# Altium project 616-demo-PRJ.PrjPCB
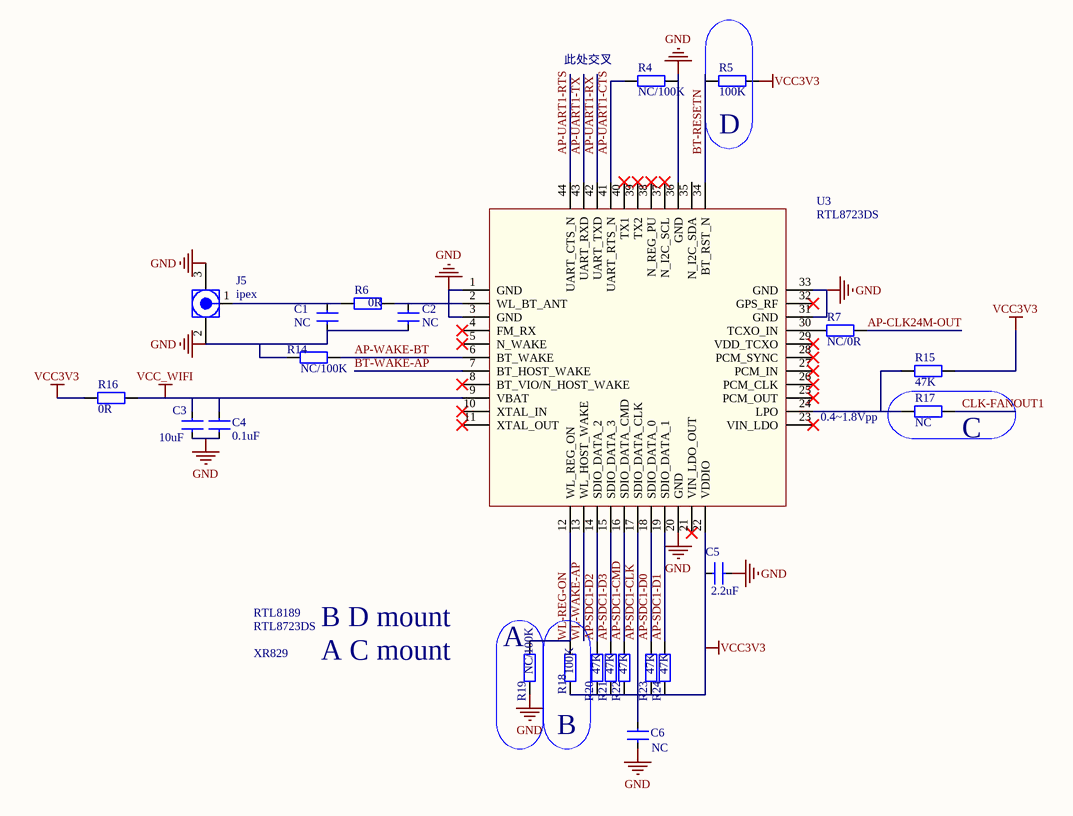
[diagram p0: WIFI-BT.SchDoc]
2 sheets, 70 parts. Net scope: global (net labels, ports and power ports of the same name join across sheets).
Board file: 616DEMO.PcbDoc
Sheets:
  WIFI-BT.SchDoc
  D1-Periph.SchDoc

## Sheet WIFI-BT.SchDoc
size A3

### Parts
C1  NC  [C0402]
C2  NC  [C0402]
C3  10uF  [C0402]
C4  0.1uF  [C0402]
C5  2.2uF  [C0402]
C6  NC  [C0402]
J5  ipex  [I-PEX SOCKET]
R4  NC/100K  [R0402]
R5  100K  [R0402]
R6  0R  [R0402]
R7  NC/0R  [R0402]
R14  NC/100K  [R0402]
R15  47K  [R0402]
R16  0R  [R0402]
R17  NC  [R0402]
R18  100K  [R0402]
R19  NC/100K  [R0402]
R20  47K  [R0402]
R21  47K  [R0402]
R22  47K  [R0402]
R23  47K  [R0402]
R24  47K  [R0402]
U3  RTL8723DS  [RTL8723DS]

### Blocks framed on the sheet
D: R5
A: R19
B: R18

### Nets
GND: C1.1 C2.1 C3.1 C4.1 C5.1 C6.1 J5.2(GND) J5.3(GND) R4.1 R14.2 R19.1 U3.1(GND) U3.3(GND) U3.20(GND) U3.31(GND) U3.33(GND) U3.36(GND)
VCC3V3: C5.2 R5.1 R15.2 R16.2 R18.1 R20.1 R21.1 R22.1 R23.1 R24.1 U3.22(VDDIO)
VCC_WIFI: C3.2 C4.2 R16.1 U3.9(VBAT)
AP-CLK24M-OUT: R7.1
AP-SDC1-CLK: C6.2 U3.17(SDIO_DATA_CLK)
AP-SDC1-CMD: R22.2 U3.16(SDIO_DATA_CMD)
AP-SDC1-D0: R23.2 U3.18(SDIO_DATA_0)
AP-SDC1-D1: R24.2 U3.19(SDIO_DATA_1)
AP-SDC1-D2: R20.2 U3.14(SDIO_DATA_2)
AP-SDC1-D3: R21.2 U3.15(SDIO_DATA_3)
AP-UART1-CTS: R4.2 U3.41(UART_RTS_N)
AP-UART1-RTS: U3.44(UART_CTS_N)
AP-UART1-RX: U3.42(UART_TXD)
AP-UART1-TX: U3.43(UART_RXD)
AP-WAKE-BT: R14.1 U3.6(BT_WAKE)
BT-RESETN: R5.2 U3.34(BT_RST_N)
BT-WAKE-AP: U3.7(BT_HOST_WAKE)
CLK-FANOUT1: R17.1
WL-REG-ON: R18.2 R19.2 U3.12(WL_REG_ON)
WL-WAKE-AP: U3.13(WL_HOST_WAKE)
NetC1_2: C1.2 J5.1(Signal) R6.2
NetC2_2: C2.2 R6.1 U3.2(WL_BT_ANT)
NetR7_2: R7.2 U3.30(TCXO_IN)
NetR15_1: R15.1 R17.2 U3.24(LPO)

Not connected (* = marked no-connect by the designer): U3 4(FM_RX)* 5(N_WAKE)* 8(BT_VIO/N_HOST_WAKE)* 10(XTAL_IN)* 11(XTAL_OUT)* 21(VIN_LDO_OUT)* 23(VIN_LDO)* 25(PCM_OUT)* 26(PCM_CLK)* 27(PCM_IN)* 28(PCM_SYNC)* 29(VDD_TCXO)* 32(GPS_RF)* 35(N_I2C_SDA) 37(N_I2C_SCL)* 38(N_REG_PU)* 39(TX2)* 40(TX1)*

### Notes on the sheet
- (near R4) 此处交叉
- 0.4
  .8Vpp
- (near R17) C
- RTL8723DS
- XR829
- RTL8189
- B D mount
- A C mount

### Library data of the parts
C1-C6 = CAP: 普通小电容
J5 = MCX_IPEX
R4-R7 R14-R24 = RES: 普通电阻
U3 = AP6212

## Sheet D1-Periph.SchDoc
size A3; DocumentNumber: 3; SheetNumber: 3; SheetTotal: 7
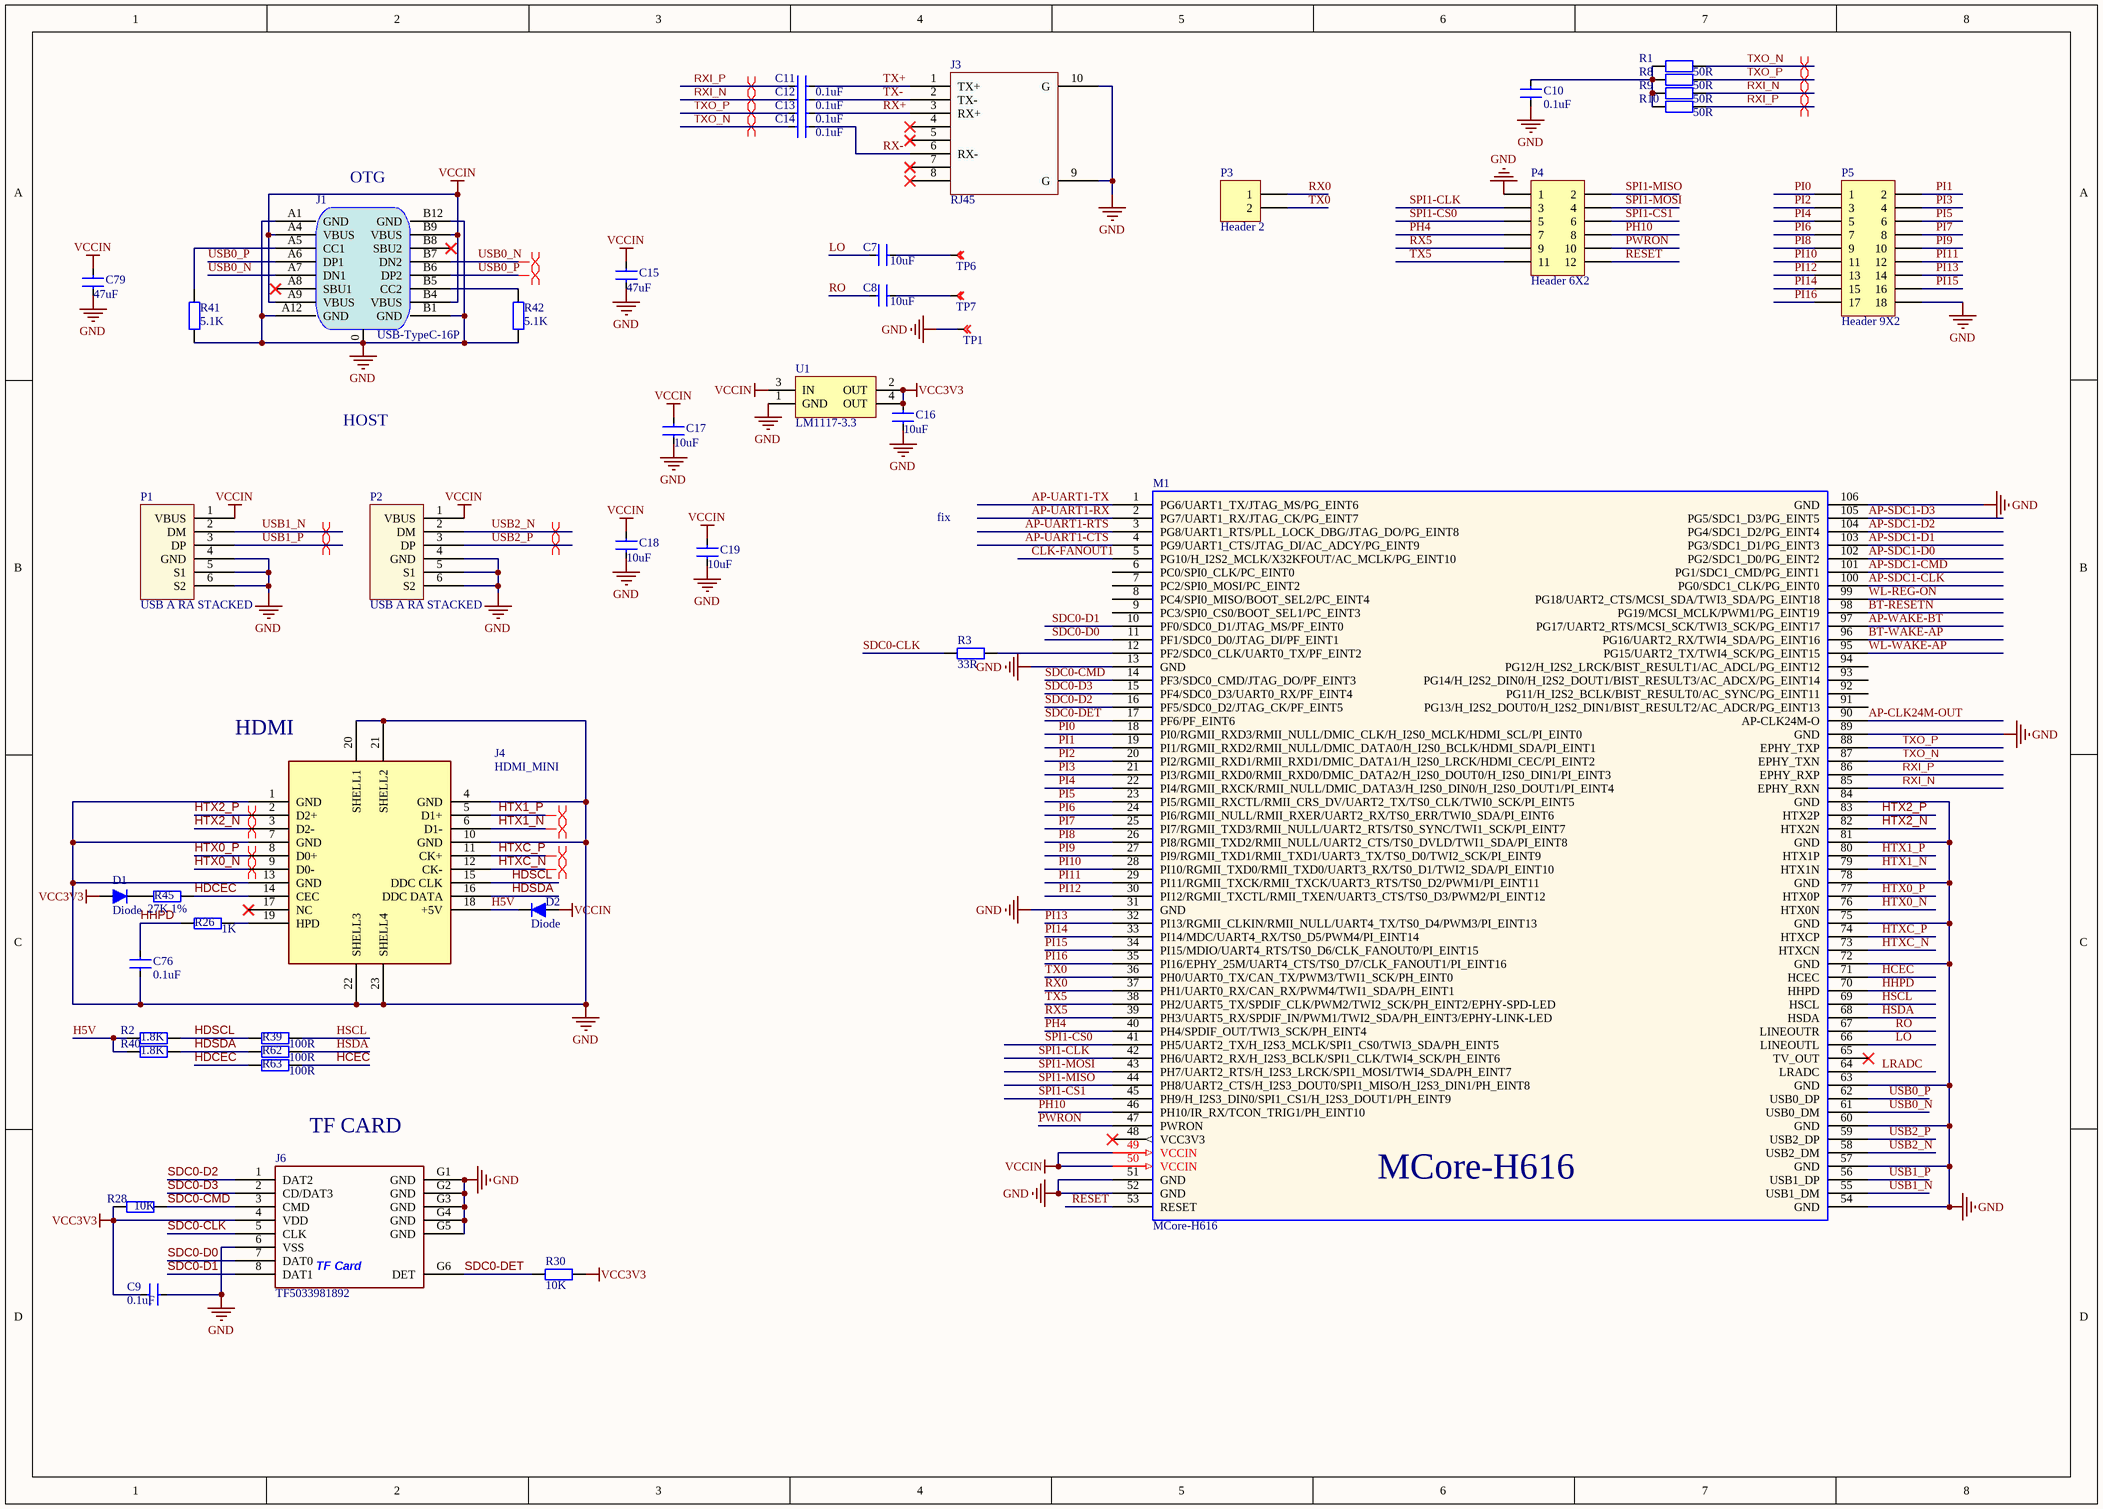
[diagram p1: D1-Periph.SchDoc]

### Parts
C7  10uF  [C0402]
C8  10uF  [C0402]
C9  0.1uF  [C0402]
C10  0.1uF  [C0402]
C11  0.1uF  [C0402]
C12  0.1uF  [C0402]
C13  0.1uF  [C0402]
C14  0.1uF  [C0402]
C15  47uF  [C0603]
C16  10uF  [C0402]
C17  10uF  [C0402]
C18  10uF  [C0402]
C19  10uF  [C0402]
C76  0.1uF  [C0402]
C79  47uF  [C0603]
D1  Diode  [SOD523]
D2  Diode  [SOD523]
J1  USB-TypeC-16P  [usb-typec-16p]
J3  RJ45  [RJ45]
J4  HDMI_MINI  [HDMI_T _mini]
J6  TF5033981892  [TFCARD-1040310811]
M1  MCore-H616  [MCore-H616]
P1  USB A RA STACKED  [USB-A STAND]
P2  USB A RA STACKED  [USB-A STAND]
P3  Header 2  [HDR1X2]
P4  Header 6X2  [HDR2X6]
P5  Header 9X2  [HDR2X9]
R1  50R  [R0402]
R2  1.8K  [R0402]
R3  33R  [R0402]
R8  50R  [R0402]
R9  50R  [R0402]
R10  50R  [R0402]
R26  1K  [R0402]
R28  10K  [R0402]
R30  10K  [R0402]
R39  100R  [R0402]
R40  1.8K  [R0402]
R41  5.1K  [R0402]
R42  5.1K  [R0402]
R45  27K 1%  [R0402]
R62  100R  [R0402]
R63  100R  [R0402]
TP1  TEST POINT  [TEST-POINT1.5]  (value not drawn)
TP6  TEST POINT  [TEST-POINT1.5]  (value not drawn)
TP7  TEST POINT  [TEST-POINT1.5]  (value not drawn)
U1  LM1117-3.3  [SOT223-4N]

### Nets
GND: C9.2 C10.1 C15.2 C16.2 C17.2 C18.2 C19.2 C76.1 C79.2 J1.0 J1.A1(GND) J1.A12(GND) J1.B1(GND) J1.B12(GND) J3.9(G) J3.10(G) J4.1(GND) J4.4(GND) J4.7(GND) J4.10(GND) J4.13(GND) J4.20(SHELL1) J4.21(SHELL2) J4.22(SHELL3) J4.23(SHELL4) J6.6(VSS) J6.G1(GND) J6.G2(GND) J6.G3(GND) J6.G4(GND) J6.G5(GND) M1.13(GND) M1.31(GND) M1.51(GND) M1.52(GND) M1.54(GND) M1.57(GND) M1.60(GND) M1.63(GND) M1.72(GND) M1.75(GND) M1.78(GND) M1.81(GND) M1.84(GND) M1.89(GND) M1.106(GND) P1.4(GND) P1.5(S1) P1.6(S2) P2.4(GND) P2.5(S1) P2.6(S2) P4.1 P5.18 R41.1 R42.1 TP1.1 U1.1(GND)
VCC3V3: C9.1 C16.1 D1.A J6.4(VDD) R28.1 R30.1 U1.2(OUT) U1.4(OUT)
VCCIN: C15.1 C17.1 C18.1 C19.1 C79.1 D2.A J1.A4(VBUS) J1.A9(VBUS) J1.B4(VBUS) J1.B9(VBUS) M1.49(VCCIN) M1.50(VCCIN) P1.1(VBUS) P2.1(VBUS) U1.3(IN)
AP-CLK24M-OUT: M1.90(AP-CLK24M-O)
AP-SDC1-CLK: M1.100(PG0/SDC1_CLK/PG_EINT0)
AP-SDC1-CMD: M1.101(PG1/SDC1_CMD/PG_EINT1)
AP-SDC1-D0: M1.102(PG2/SDC1_D0/PG_EINT2)
AP-SDC1-D1: M1.103(PG3/SDC1_D1/PG_EINT3)
AP-SDC1-D2: M1.104(PG4/SDC1_D2/PG_EINT4)
AP-SDC1-D3: M1.105(PG5/SDC1_D3/PG_EINT5)
AP-UART1-CTS: M1.4(PG9/UART1_CTS/JTAG_DI/AC_ADCY/PG_EINT9)
AP-UART1-RTS: M1.3(PG8/UART1_RTS/PLL_LOCK_DBG/JTAG_DO/PG_EINT8)
AP-UART1-RX: M1.2(PG7/UART1_RX/JTAG_CK/PG_EINT7)
AP-UART1-TX: M1.1(PG6/UART1_TX/JTAG_MS/PG_EINT6)
AP-WAKE-BT: M1.97(PG17/UART2_RTS/MCSI_SCK/TWI3_SCK/PG_EINT17)
BT-RESETN: M1.98(PG19/MCSI_MCLK/PWM1/PG_EINT19)
BT-WAKE-AP: M1.96(PG16/UART2_RX/TWI4_SDA/PG_EINT16)
CLK-FANOUT1: M1.5(PG10/H_I2S2_MCLK/X32KFOUT/AC_MCLK/PG_EINT10)
H5V: D2.K J4.18(+5V) R2.1 R40.1
HCEC: M1.71(HCEC) R63.1
HDCEC: J4.14(CEC) R45.1 R63.2
HDSCL: J4.15(DDC_CLK) R2.2 R39.2
HDSDA: J4.16(DDC_DATA) R40.2 R62.2
HHPD: C76.2 M1.70(HHPD) R26.2
HSCL: M1.69(HSCL) R39.1
HSDA: M1.68(HSDA) R62.1
HTX0_N: J4.9(D0-) M1.76(HTX0N)
HTX0_P: J4.8(D0+) M1.77(HTX0P)
HTX1_N: J4.6(D1-) M1.79(HTX1N)
HTX1_P: J4.5(D1+) M1.80(HTX1P)
HTX2_N: J4.3(D2-) M1.82(HTX2N)
HTX2_P: J4.2(D2+) M1.83(HTX2P)
HTXC_N: J4.12(CK-) M1.73(HTXCN)
HTXC_P: J4.11(CK+) M1.74(HTXCP)
LO: C7.1 M1.66(LINEOUTL)
LRADC: M1.64(LRADC)
PH4: M1.40(PH4/SPDIF_OUT/TWI3_SCK/PH_EINT4) P4.7
PH10: M1.46(PH10/IR_RX/TCON_TRIG1/PH_EINT10) P4.8
PI0: M1.18(PI0/RGMII_RXD3/RMII_NULL/DMIC_CLK/H_I2S0_MCLK/HDMI_SCL/PI_EINT0) P5.1
PI1: M1.19(PI1/RGMII_RXD2/RMII_NULL/DMIC_DATA0/H_I2S0_BCLK/HDMI_SDA/PI_EINT1) P5.2
PI2: M1.20(PI2/RGMII_RXD1/RMII_RXD1/DMIC_DATA1/H_I2S0_LRCK/HDMI_CEC/PI_EINT2) P5.3
PI3: M1.21(PI3/RGMII_RXD0/RMII_RXD0/DMIC_DATA2/H_I2S0_DOUT0/H_I2S0_DIN1/PI_EINT3) P5.4
PI4: M1.22(PI4/RGMII_RXCK/RMII_NULL/DMIC_DATA3/H_I2S0_DIN0/H_I2S0_DOUT1/PI_EINT4) P5.5
PI5: M1.23(PI5/RGMII_RXCTL/RMII_CRS_DV/UART2_TX/TS0_CLK/TWI0_SCK/PI_EINT5) P5.6
PI6: M1.24(PI6/RGMII_NULL/RMII_RXER/UART2_RX/TS0_ERR/TWI0_SDA/PI_EINT6) P5.7
PI7: M1.25(PI7/RGMII_TXD3/RMII_NULL/UART2_RTS/TS0_SYNC/TWI1_SCK/PI_EINT7) P5.8
PI8: M1.26(PI8/RGMII_TXD2/RMII_NULL/UART2_CTS/TS0_DVLD/TWI1_SDA/PI_EINT8) P5.9
PI9: M1.27(PI9/RGMII_TXD1/RMII_TXD1/UART3_TX/TS0_D0/TWI2_SCK/PI_EINT9) P5.10
PI10: M1.28(PI10/RGMII_TXD0/RMII_TXD0/UART3_RX/TS0_D1/TWI2_SDA/PI_EINT10) P5.11
PI11: M1.29(PI11/RGMII_TXCK/RMII_TXCK/UART3_RTS/TS0_D2/PWM1/PI_EINT11) P5.12
PI12: M1.30(PI12/RGMII_TXCTL/RMII_TXEN/UART3_CTS/TS0_D3/PWM2/PI_EINT12) P5.13
PI13: M1.32(PI13/RGMII_CLKIN/RMII_NULL/UART4_TX/TS0_D4/PWM3/PI_EINT13) P5.14
PI14: M1.33(PI14/MDC/UART4_RX/TS0_D5/PWM4/PI_EINT14) P5.15
PI15: M1.34(PI15/MDIO/UART4_RTS/TS0_D6/CLK_FANOUT0/PI_EINT15) P5.16
PI16: M1.35(PI16/EPHY_25M/UART4_CTS/TS0_D7/CLK_FANOUT1/PI_EINT16) P5.17
PWRON: M1.47(PWRON) P4.10
RESET: M1.53(RESET) P4.12
RO: C8.1 M1.67(LINEOUTR)
RX0: M1.37(PH1/UART0_RX/CAN_RX/PWM4/TWI1_SDA/PH_EINT1) P3.1
RX5: M1.39(PH3/UART5_RX/SPDIF_IN/PWM1/TWI2_SDA/PH_EINT3/EPHY-LINK-LED) P4.9
RX+: C13.2 J3.3(RX+)
RX-: C14.2 J3.6(RX-)
RXI_N: C12.1 M1.85(EPHY_RXN) R9.1
RXI_P: C11.1 M1.86(EPHY_RXP) R10.1
SDC0-CLK: J6.5(CLK) R3.2
SDC0-CMD: J6.3(CMD) M1.14(PF3/SDC0_CMD/JTAG_DO/PF_EINT3) R28.2
SDC0-D0: J6.7(DAT0) M1.11(PF1/SDC0_D0/JTAG_DI/PF_EINT1)
SDC0-D1: J6.8(DAT1) M1.10(PF0/SDC0_D1/JTAG_MS/PF_EINT0)
SDC0-D2: J6.1(DAT2) M1.16(PF5/SDC0_D2/JTAG_CK/PF_EINT5)
SDC0-D3: J6.2(CD/DAT3) M1.15(PF4/SDC0_D3/UART0_RX/PF_EINT4)
SDC0-DET: J6.G6(DET) M1.17(PF6/PF_EINT6) R30.2
SPI1-CLK: M1.42(PH6/UART2_RX/H_I2S3_BCLK/SPI1_CLK/TWI4_SCK/PH_EINT6) P4.3
SPI1-CS0: M1.41(PH5/UART2_TX/H_I2S3_MCLK/SPI1_CS0/TWI3_SDA/PH_EINT5) P4.5
SPI1-CS1: M1.45(PH9/H_I2S3_DIN0/SPI1_CS1/H_I2S3_DOUT1/PH_EINT9) P4.6
SPI1-MISO: M1.44(PH8/UART2_CTS/H_I2S3_DOUT0/SPI1_MISO/H_I2S3_DIN1/PH_EINT8) P4.2
SPI1-MOSI: M1.43(PH7/UART2_RTS/H_I2S3_LRCK/SPI1_MOSI/TWI4_SDA/PH_EINT7) P4.4
TX0: M1.36(PH0/UART0_TX/CAN_TX/PWM3/TWI1_SCK/PH_EINT0) P3.2
TX5: M1.38(PH2/UART5_TX/SPDIF_CLK/PWM2/TWI2_SCK/PH_EINT2/EPHY-SPD-LED) P4.11
TX+: C11.2 J3.1(TX+)
TX-: C12.2 J3.2(TX-)
TXO_N: C14.1 M1.87(EPHY_TXN) R1.1
TXO_P: C13.1 M1.88(EPHY_TXP) R8.1
USB0_N: J1.A7(DN1) J1.B7(DN2) M1.61(USB0_DM)
USB0_P: J1.A6(DP1) J1.B6(DP2) M1.62(USB0_DP)
USB1_N: M1.55(USB1_DM) P1.2(DM)
USB1_P: M1.56(USB1_DP) P1.3(DP)
USB2_N: M1.58(USB2_DM) P2.2(DM)
USB2_P: M1.59(USB2_DP) P2.3(DP)
WL-REG-ON: M1.99(PG18/UART2_CTS/MCSI_SDA/TWI3_SDA/PG_EINT18)
WL-WAKE-AP: M1.95(PG15/UART2_TX/TWI4_SCK/PG_EINT15)
NetC7_2: C7.2 TP6.1
NetC8_2: C8.2 TP7.1
NetC10_2: C10.2 R1.2 R8.2 R9.2 R10.2
NetD1_K: D1.K R45.2
NetJ1_A5: J1.A5(CC1) R41.2
NetJ1_B5: J1.B5(CC2) R42.2
NetJ4_19: J4.19(HPD) R26.1
NetM1_12: M1.12(PF2/SDC0_CLK/UART0_TX/PF_EINT2) R3.1

Not connected (* = marked no-connect by the designer): J1 A8(SBU1)* B8(SBU2)*; J3 4* 5* 7* 8*; J4 17(NC)*; M1 6(PC0/SPI0_CLK/PC_EINT0) 7(PC2/SPI0_MOSI/PC_EINT2) 8(PC4/SPI0_MISO/BOOT_SEL2/PC_EINT4) 9(PC3/SPI0_CS0/BOOT_SEL1/PC_EINT3) 48(VCC3V3)* 65(TV_OUT)* 91(PG13/H_I2S2_DOUT0/H_I2S2_DIN1/BIST_RESULT2/AC_ADCR/PG_EINT13) 92(PG11/H_I2S2_BCLK/BIST_RESULT0/AC_SYNC/PG_EINT11) 93(PG14/H_I2S2_DIN0/H_I2S2_DOUT1/BIST_RESULT3/AC_ADCX/PG_EINT14) 94(PG12/H_I2S2_LRCK/BIST_RESULT1/AC_ADCL/PG_EINT12)

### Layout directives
differential pair: HTX0_N, HTX0_P, HTX1_N, HTX1_P, HTX2_N, HTX2_P, HTXC_N, HTXC_P, RXI_N, RXI_P, TXO_N, TXO_P, USB0_N, USB0_P, USB1_N, USB1_P, USB2_N, USB2_P

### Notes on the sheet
- (near J1) OTG
- HOST
- fix
- (near J4) HDMI
- TF CARD

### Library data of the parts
C7-C19 C76 C79 = CAP: 普通小电容
D1 D2 = Diode: 普通二极管
J3 = RJ45: RJ45不带网络变压器
P1 P2 = USB A Right Angle Stacked: CONN RECEPT STACKED USB A RT ANG
P3 = Header 2: Header, 2-Pin
P4 = Header 6X2: Header, 6-Pin, Dual row
P5 = Header 9X2: Header, 9-Pin, Dual row
R1-R3 R8-R10 R26 R28 R30 R39-R42 R45 R62 R63 = RES: 普通电阻
TP1 TP6 TP7 = TP: Description
U1 = LM1117-3.3: 800mA and 1A Low Dropout Positive Regulator 2.85V, 3.3V, 5V, and Adjustable; PackageDocument: revC

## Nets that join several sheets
GND: WIFI-BT (17 pins), D1-Periph (58 pins)
VCC3V3: WIFI-BT (11 pins), D1-Periph (8 pins)
AP-CLK24M-OUT: WIFI-BT (R7.1), D1-Periph (M1.90)
AP-SDC1-CLK: WIFI-BT (C6.2 U3.17), D1-Periph (M1.100)
AP-SDC1-CMD: WIFI-BT (R22.2 U3.16), D1-Periph (M1.101)
AP-SDC1-D0: WIFI-BT (R23.2 U3.18), D1-Periph (M1.102)
AP-SDC1-D1: WIFI-BT (R24.2 U3.19), D1-Periph (M1.103)
AP-SDC1-D2: WIFI-BT (R20.2 U3.14), D1-Periph (M1.104)
AP-SDC1-D3: WIFI-BT (R21.2 U3.15), D1-Periph (M1.105)
AP-UART1-CTS: WIFI-BT (R4.2 U3.41), D1-Periph (M1.4)
AP-UART1-RTS: WIFI-BT (U3.44), D1-Periph (M1.3)
AP-UART1-RX: WIFI-BT (U3.42), D1-Periph (M1.2)
AP-UART1-TX: WIFI-BT (U3.43), D1-Periph (M1.1)
AP-WAKE-BT: WIFI-BT (R14.1 U3.6), D1-Periph (M1.97)
BT-RESETN: WIFI-BT (R5.2 U3.34), D1-Periph (M1.98)
BT-WAKE-AP: WIFI-BT (U3.7), D1-Periph (M1.96)
CLK-FANOUT1: WIFI-BT (R17.1), D1-Periph (M1.5)
WL-REG-ON: WIFI-BT (R18.2 R19.2 U3.12), D1-Periph (M1.99)
WL-WAKE-AP: WIFI-BT (U3.13), D1-Periph (M1.95)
